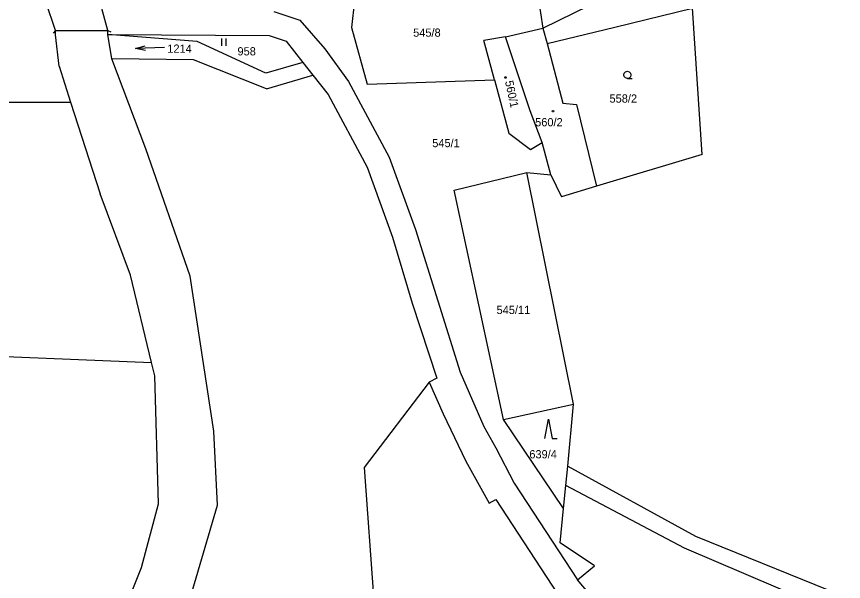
# Model space of a CAD drawing. Extents: x -812394 to -807601, y -1013097 to -1009266.
# Drawn here: x -809003.5 to -808832.6, y -1011807.5 to -1011690.8 of the extents above; entities that cross this region are included whole.
import ezdxf

# ---------------------------------------------------------------- set-up
doc = ezdxf.new("R2010")
doc.units = 0
for name, color, linetype in [('Default', 7, 'Continuous'), ('KN_HRANICE', 7, 'Continuous'), ('KN_KULTURY', 7, 'Continuous'), ('KN_PARCELY', 7, 'Continuous'), ('KN_SLUCKY', 7, 'Continuous')]:
    doc.layers.add(name, color=color, linetype=linetype)

# ---------------------------------------------------------------- blocks, each defined once
blk = doc.blocks.new('4201')
at = {"layer": 'Default'}
blk.add_line((0, 0), (-0.5, -0.5), dxfattribs=at)
blk = doc.blocks.new('304')
at = {"layer": 'Default'}
blk.add_lwpolyline([(0, 0), (-0.38, 0.1), (-0.65, 0.37), (-0.75, 0.74), (-0.65, 1.11), (-0.38, 1.38), (-0.01, 1.48), (0.36, 1.38), (0.63, 1.11), (0.73, 0.73), (0.63, 0.35), (0.36, 0.08), (-0.02, -0.02), (0.98, -0.02)], dxfattribs=at)
blk = doc.blocks.new('306')
at = {"layer": 'Default'}
for p, q in [((-0.5, 1.5), (-0.5, 0)), ((0.5, 0), (0.5, 1.5))]:
    blk.add_line(p, q, dxfattribs=at)
blk = doc.blocks.new('308')
at = {"layer": 'Default'}
blk.add_lwpolyline([(-0.75, 0), (0, 4), (0.75, 0), (1.75, 0)], dxfattribs=at)
blk = doc.blocks.new('NAHRADNI_SYMBOL')
at = {"layer": 'Default'}
blk.add_lwpolyline([(0.09, 0.15), (0.18, 0), (0.09, -0.15), (-0.09, -0.15), (-0.18, 0), (-0.09, 0.15), (0.09, 0.15)], dxfattribs=at)
blk = doc.blocks.new('802')
at = {"layer": 'Default'}
blk.add_line((-3, 0), (3, 0), dxfattribs=at)
blk.add_lwpolyline([(1, 0.5), (3, 0), (1, -0.5)], dxfattribs=at)

msp = doc.modelspace()

# ---------------------------------------------------------------- linework, layer by layer
at = {"layer": 'KN_HRANICE'}
for p, q in [((-808896.85, -1011679.68), (-808894.75, -1011693.18)), ((-808894.75, -1011693.18), (-808871.71, -1011681.7)), ((-808995.44, -1011693.68), (-808997.44, -1011687.71)), ((-808984.63, -1011693.65), (-808986.26, -1011687.57)), ((-808933.67, -1011687.5), (-808934.28, -1011693.03)), ((-808879.89, -1011692.95), (-808863.84, -1011689.06)), ((-808861.85, -1011719.28), (-808863.84, -1011689.06)), ((-808950.35, -1011689.74), (-808944.94, -1011691.54)), ((-808944.94, -1011691.54), (-808939.79, -1011697.43)), ((-808995.44, -1011694.53), (-808995.44, -1011693.68)), ((-808984.63, -1011694.5), (-808984.63, -1011693.65)), ((-808934.28, -1011693.03), (-808931.07, -1011704.75)), ((-808902.44, -1011694.98), (-808894.75, -1011693.18)), ((-808894.75, -1011693.18), (-808893.86, -1011696.32)), ((-808893.86, -1011696.32), (-808879.89, -1011692.95)), ((-808994.72, -1011701.03), (-808995.44, -1011694.53)), ((-808984.63, -1011694.5), (-808951.31, -1011694.69)), ((-808966.16, -1011695.95), (-808984.63, -1011694.5)), ((-808983.84, -1011699.49), (-808984.63, -1011694.5)), ((-808951.96, -1011702.46), (-808966.16, -1011695.95)), ((-808951.31, -1011694.69), (-808947.81, -1011695.86)), ((-808947.81, -1011695.86), (-808944.33, -1011700.27)), ((-808902.44, -1011694.98), (-808906.94, -1011695.74)), ((-808904.75, -1011703.86), (-808906.94, -1011695.74)), ((-808897.41, -1011710.26), (-808902.44, -1011694.98)), ((-808939.79, -1011697.43), (-808934.88, -1011704.2)), ((-808893.86, -1011696.32), (-808890.65, -1011708.71)), ((-808994.72, -1011701.03), (-808992.34, -1011708.44)), ((-808944.33, -1011700.27), (-808951.96, -1011702.46)), ((-808944.33, -1011700.27), (-808942.28, -1011702.87)), ((-808951.87, -1011705.7), (-808942.28, -1011702.87)), ((-808942.28, -1011702.87), (-808939.13, -1011706.86)), ((-808934.88, -1011704.2), (-808926.48, -1011719.85)), ((-808931.07, -1011704.75), (-808904.75, -1011703.86)), ((-808904.75, -1011703.86), (-808901.77, -1011714.86)), ((-808939.13, -1011706.86), (-808931.06, -1011721.89)), ((-809019.35, -1011708.55), (-808992.34, -1011708.44)), ((-808992.34, -1011708.44), (-808986.23, -1011727.44)), ((-808890.65, -1011708.71), (-808887.77, -1011708.95)), ((-808887.77, -1011708.95), (-808883.64, -1011725.86)), ((-808894.93, -1011716.8), (-808897.41, -1011710.26)), ((-808901.77, -1011714.86), (-808897.28, -1011718.24)), ((-808897.28, -1011718.24), (-808894.93, -1011716.8)), ((-808893.13, -1011723.47), (-808894.93, -1011716.8)), ((-808926.48, -1011719.85), (-808921.09, -1011734.77)), ((-808861.85, -1011719.28), (-808883.64, -1011725.86)), ((-808931.06, -1011721.89), (-808925.84, -1011736.34)), ((-808913.07, -1011726.68), (-808898.05, -1011723.01)), ((-808888.39, -1011770.88), (-808898.05, -1011723.01)), ((-808898.05, -1011723.01), (-808893.13, -1011723.47)), ((-808893.13, -1011723.47), (-808890.89, -1011728.05)), ((-808902.86, -1011774.06), (-808913.07, -1011726.68)), ((-808883.64, -1011725.86), (-808890.89, -1011728.05)), ((-808979.98, -1011744.21), (-808986.23, -1011727.44)), ((-808921.09, -1011734.77), (-808911.81, -1011764.29)), ((-808925.84, -1011736.34), (-808921.75, -1011749.99)), ((-808975.59, -1011762.27), (-808979.98, -1011744.21)), ((-808921.75, -1011749.99), (-808916.67, -1011765.52)), ((-809026.09, -1011760.16), (-808975.59, -1011762.27)), ((-808974.91, -1011765.05), (-808975.59, -1011762.27)), ((-808911.81, -1011764.29), (-808906.98, -1011775.5)), ((-808974.17, -1011791.5), (-808974.91, -1011765.05)), ((-808916.67, -1011765.52), (-808918.26, -1011766.3)), ((-808918.26, -1011766.3), (-808931.65, -1011783.96)), ((-808918.26, -1011766.3), (-808915.32, -1011772.9)), ((-808902.86, -1011774.06), (-808888.39, -1011770.88)), ((-808889.62, -1011783.66), (-808888.39, -1011770.88)), ((-808915.32, -1011772.9), (-808910.67, -1011782.65)), ((-808890.47, -1011792.42), (-808902.86, -1011774.06)), ((-808906.98, -1011775.5), (-808904.48, -1011779.89)), ((-808904.48, -1011779.89), (-808900.69, -1011787.19)), ((-808910.67, -1011782.65), (-808905.83, -1011791.31)), ((-808931.65, -1011783.96), (-808923.83, -1011891.74)), ((-808890.01, -1011787.67), (-808889.62, -1011783.66)), ((-808889.62, -1011783.66), (-808863.23, -1011798.16)), ((-808900.69, -1011787.19), (-808887.62, -1011807.14)), ((-808890.47, -1011792.42), (-808890.01, -1011787.67)), ((-808865.49, -1011800.66), (-808890.01, -1011787.67)), ((-808977.69, -1011804.62), (-808974.17, -1011791.5)), ((-808905.83, -1011791.31), (-808904.46, -1011790.57)), ((-808904.46, -1011790.57), (-808891.7, -1011810.04)), ((-808891.16, -1011799.52), (-808890.47, -1011792.42)), ((-808863.23, -1011798.16), (-808822.56, -1011814.57)), ((-808884.06, -1011804.26), (-808891.16, -1011799.52)), ((-808824.78, -1011817.93), (-808865.49, -1011800.66)), ((-808986.12, -1011825.88), (-808977.69, -1011804.62)), ((-808887.62, -1011807.14), (-808884.06, -1011804.26)), ((-808878.74, -1011817.7), (-808887.62, -1011807.14))]:
    msp.add_line(p, q, dxfattribs=at)
for points in [[(-808951.87, -1011705.7), (-808966.96, -1011699.71), (-808983.84, -1011699.49)], [(-808959.35, -1011971.59), (-808962.28, -1011929.28), (-808966.55, -1011904.05), (-808970.77, -1011886.31), (-808975.49, -1011831.97), (-808967.41, -1011810.26), (-808962, -1011791.72), (-808962.72, -1011776.44), (-808967.65, -1011744.41), (-808976.79, -1011718.1), (-808983.84, -1011699.49)]]:
    msp.add_lwpolyline(points, dxfattribs=at)
at = {"layer": 'KN_SLUCKY'}
msp.add_line((-808995.44, -1011693.68), (-808984.63, -1011693.65), dxfattribs=at)

# ---------------------------------------------------------------- block references
at = {"layer": 'KN_KULTURY'}
for name, p in [('306', (-808960.66, -1011696.83)), ('304', (-808877.28, -1011703.56)), ('NAHRADNI_SYMBOL', (-808902.48, -1011703.36)), ('NAHRADNI_SYMBOL', (-808892.64, -1011710.33)), ('308', (-808893.57, -1011777.97))]:
    msp.add_blockref(name, p, dxfattribs=at)
at = {"layer": 'KN_KULTURY', "rotation": -178.25778700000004}
msp.add_blockref('802', (-808975.9, -1011697.27), dxfattribs=at)
at = {"layer": 'KN_SLUCKY'}
msp.add_blockref('4201', (-808995.44, -1011693.68), dxfattribs=at)
at = {"layer": 'KN_SLUCKY', "rotation": 108.91927700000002}
msp.add_blockref('4201', (-808984.63, -1011693.65), dxfattribs=at)

# ---------------------------------------------------------------- texts
at = {"layer": 'KN_PARCELY'}
for s, p in [('545/8', (-808921.56, -1011694.95)), ('1214', (-808972.35, -1011698.26)), ('958', (-808957.85, -1011698.81)), ('558/2', (-808880.98, -1011708.57)), ('560/2', (-808896.35, -1011713.46)), ('545/1', (-808917.61, -1011717.77)), ('545/11', (-808904.32, -1011752.25)), ('639/4', (-808897.55, -1011782.07))]:
    msp.add_text(s, height=1.7, dxfattribs=at).set_placement(p)
msp.add_text('560/1', height=1.7, rotation=282.067, dxfattribs=at).set_placement((-808902.58, -1011704.19))

doc.saveas('drawing.dxf')
